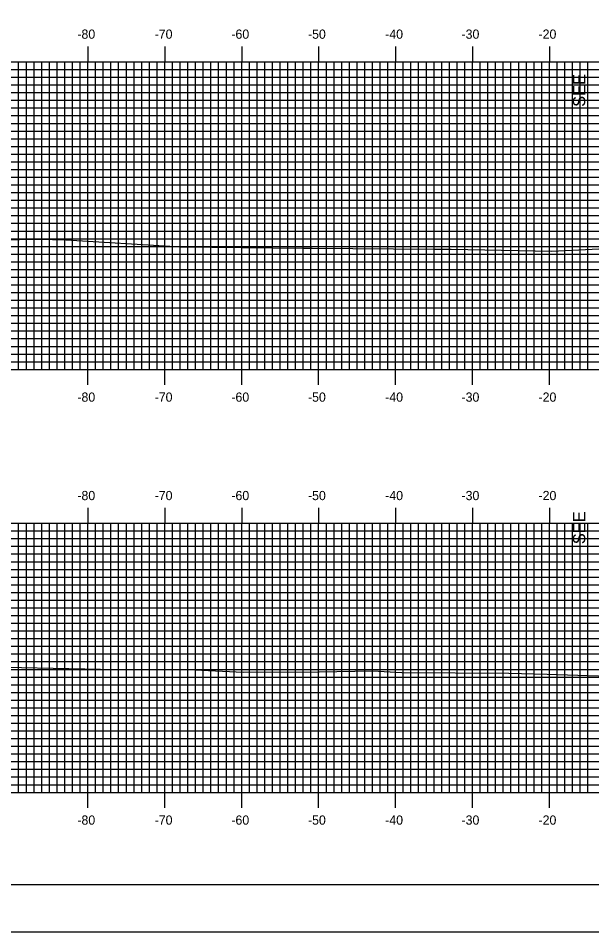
# Model space of a CAD drawing. Extents: x 854903 to 855247, y 364366 to 364586.
# Drawn here: x 854980.2 to 855054.8, y 364365.7 to 364484.5 of the extents above; entities that cross this region are included whole.
import ezdxf

# ---------------------------------------------------------------- set-up
doc = ezdxf.new("R2010")
doc.units = 0
for name, color, linetype in [('ANNOTATION', 7, 'Continuous'), ('BORDER', 7, 'Continuous'), ('H_V ANNOTATION', 7, 'Continuous'), ('MAJOR', 7, 'Continuous'), ('MINOR', 7, 'Continuous'), ('PLOT BOUNDARY', 7, 'Continuous'), ('S_Roadway_Centerline', 7, 'Continuous')]:
    doc.layers.add(name, color=color, linetype=linetype)

msp = doc.modelspace()

# ---------------------------------------------------------------- linework, layer by layer
at = {"layer": 'BORDER'}
msp.add_lwpolyline([(854919.66, 364371.79), (855239.66, 364371.79), (855239.66, 364581.79), (854919.66, 364581.79)], close=True, dxfattribs=at)
at = {"layer": 'MAJOR'}
for p, q in [((854989.26, 364480.79), (854989.26, 364478.79)), ((854999.26, 364480.79), (854999.26, 364478.79)), ((855009.26, 364480.79), (855009.26, 364478.79)), ((855019.26, 364480.79), (855019.26, 364478.79)), ((855029.26, 364480.79), (855029.26, 364478.79)), ((855039.26, 364480.79), (855039.26, 364478.79)), ((855049.26, 364480.79), (855049.26, 364478.79)), ((854929.26, 364478.79), (855209.26, 364478.79)), ((854929.26, 364478.79), (855209.26, 364478.79)), ((854989.26, 364438.79), (854989.26, 364478.79)), ((854999.26, 364438.79), (854999.26, 364478.79)), ((855009.26, 364438.79), (855009.26, 364478.79)), ((855019.26, 364438.79), (855019.26, 364478.79)), ((855029.26, 364438.79), (855029.26, 364478.79)), ((855039.26, 364438.79), (855039.26, 364478.79)), ((855049.26, 364438.79), (855049.26, 364478.79)), ((854929.26, 364473.79), (855209.26, 364473.79)), ((854929.26, 364468.79), (855209.26, 364468.79)), ((854929.26, 364463.79), (855209.26, 364463.79)), ((854929.26, 364458.79), (855209.26, 364458.79)), ((854929.26, 364453.79), (855209.26, 364453.79)), ((854929.26, 364448.79), (855209.26, 364448.79)), ((854929.26, 364443.79), (855209.26, 364443.79)), ((854929.26, 364438.79), (855209.26, 364438.79)), ((854929.26, 364438.79), (855209.26, 364438.79)), ((854989.26, 364436.78), (854989.26, 364438.79)), ((854999.26, 364436.78), (854999.26, 364438.79)), ((855009.26, 364436.78), (855009.26, 364438.79)), ((855019.26, 364436.78), (855019.26, 364438.79)), ((855029.26, 364436.78), (855029.26, 364438.79)), ((855039.26, 364436.78), (855039.26, 364438.79)), ((855049.26, 364436.78), (855049.26, 364438.79)), ((854989.26, 364420.79), (854989.26, 364418.79)), ((854999.26, 364420.79), (854999.26, 364418.79)), ((855009.26, 364420.79), (855009.26, 364418.79)), ((855019.26, 364420.79), (855019.26, 364418.79)), ((855029.26, 364420.79), (855029.26, 364418.79)), ((855039.26, 364420.79), (855039.26, 364418.79)), ((855049.26, 364420.79), (855049.26, 364418.79)), ((854929.26, 364418.79), (855209.26, 364418.79)), ((854929.26, 364418.79), (855209.26, 364418.79)), ((854989.26, 364383.79), (854989.26, 364418.79)), ((854999.26, 364383.79), (854999.26, 364418.79)), ((855009.26, 364383.79), (855009.26, 364418.79)), ((855019.26, 364383.79), (855019.26, 364418.79)), ((855029.26, 364383.79), (855029.26, 364418.79)), ((855039.26, 364383.79), (855039.26, 364418.79)), ((855049.26, 364383.79), (855049.26, 364418.79)), ((854929.26, 364413.79), (855209.26, 364413.79)), ((854929.26, 364408.79), (855209.26, 364408.79)), ((854929.26, 364403.79), (855209.26, 364403.79)), ((854929.26, 364398.79), (855209.26, 364398.79)), ((854929.26, 364393.79), (855209.26, 364393.79)), ((854929.26, 364388.79), (855209.26, 364388.79)), ((854929.26, 364383.79), (855209.26, 364383.79)), ((854929.26, 364383.79), (855209.26, 364383.79)), ((854989.26, 364381.78), (854989.26, 364383.79)), ((854999.26, 364381.78), (854999.26, 364383.79)), ((855009.26, 364381.78), (855009.26, 364383.79)), ((855019.26, 364381.78), (855019.26, 364383.79)), ((855029.26, 364381.78), (855029.26, 364383.79)), ((855039.26, 364381.78), (855039.26, 364383.79)), ((855049.26, 364381.78), (855049.26, 364383.79))]:
    msp.add_line(p, q, dxfattribs=at)
at = {"layer": 'MINOR'}
for p, q in [((854980.26, 364438.79), (854980.26, 364478.79)), ((854981.26, 364438.79), (854981.26, 364478.79)), ((854982.26, 364438.79), (854982.26, 364478.79)), ((854983.26, 364438.79), (854983.26, 364478.79)), ((854984.26, 364438.79), (854984.26, 364478.79)), ((854985.26, 364438.79), (854985.26, 364478.79)), ((854986.26, 364438.79), (854986.26, 364478.79)), ((854987.26, 364438.79), (854987.26, 364478.79)), ((854988.26, 364438.79), (854988.26, 364478.79)), ((854990.26, 364438.79), (854990.26, 364478.79)), ((854991.26, 364438.79), (854991.26, 364478.79)), ((854992.26, 364438.79), (854992.26, 364478.79)), ((854993.26, 364438.79), (854993.26, 364478.79)), ((854994.26, 364438.79), (854994.26, 364478.79)), ((854995.26, 364438.79), (854995.26, 364478.79)), ((854996.26, 364438.79), (854996.26, 364478.79)), ((854997.26, 364438.79), (854997.26, 364478.79)), ((854998.26, 364438.79), (854998.26, 364478.79)), ((855000.26, 364438.79), (855000.26, 364478.79)), ((855001.26, 364438.79), (855001.26, 364478.79)), ((855002.26, 364438.79), (855002.26, 364478.79)), ((855003.26, 364438.79), (855003.26, 364478.79)), ((855004.26, 364438.79), (855004.26, 364478.79)), ((855005.26, 364438.79), (855005.26, 364478.79)), ((855006.26, 364438.79), (855006.26, 364478.79)), ((855007.26, 364438.79), (855007.26, 364478.79)), ((855008.26, 364438.79), (855008.26, 364478.79)), ((855010.26, 364438.79), (855010.26, 364478.79)), ((855011.26, 364438.79), (855011.26, 364478.79)), ((855012.26, 364438.79), (855012.26, 364478.79)), ((855013.26, 364438.79), (855013.26, 364478.79)), ((855014.26, 364438.79), (855014.26, 364478.79)), ((855015.26, 364438.79), (855015.26, 364478.79)), ((855016.26, 364438.79), (855016.26, 364478.79)), ((855017.26, 364438.79), (855017.26, 364478.79)), ((855018.26, 364438.79), (855018.26, 364478.79)), ((855020.26, 364438.79), (855020.26, 364478.79)), ((855021.26, 364438.79), (855021.26, 364478.79)), ((855022.26, 364438.79), (855022.26, 364478.79)), ((855023.26, 364438.79), (855023.26, 364478.79)), ((855024.26, 364438.79), (855024.26, 364478.79)), ((855025.26, 364438.79), (855025.26, 364478.79)), ((855026.26, 364438.79), (855026.26, 364478.79)), ((855027.26, 364438.79), (855027.26, 364478.79)), ((855028.26, 364438.79), (855028.26, 364478.79)), ((855030.26, 364438.79), (855030.26, 364478.79)), ((855031.26, 364438.79), (855031.26, 364478.79)), ((855032.26, 364438.79), (855032.26, 364478.79)), ((855033.26, 364438.79), (855033.26, 364478.79)), ((855034.26, 364438.79), (855034.26, 364478.79)), ((855035.26, 364438.79), (855035.26, 364478.79)), ((855036.26, 364438.79), (855036.26, 364478.79)), ((855037.26, 364438.79), (855037.26, 364478.79)), ((855038.26, 364438.79), (855038.26, 364478.79)), ((855040.26, 364438.79), (855040.26, 364478.79)), ((855041.26, 364438.79), (855041.26, 364478.79)), ((855042.26, 364438.79), (855042.26, 364478.79)), ((855043.26, 364438.79), (855043.26, 364478.79)), ((855044.26, 364438.79), (855044.26, 364478.79)), ((855045.26, 364438.79), (855045.26, 364478.79)), ((855046.26, 364438.79), (855046.26, 364478.79)), ((855047.26, 364438.79), (855047.26, 364478.79)), ((855048.26, 364438.79), (855048.26, 364478.79)), ((855050.26, 364438.79), (855050.26, 364478.79)), ((855051.26, 364438.79), (855051.26, 364478.79)), ((855052.26, 364438.79), (855052.26, 364478.79)), ((855053.26, 364438.79), (855053.26, 364478.79)), ((855054.26, 364438.79), (855054.26, 364478.79)), ((854929.26, 364477.79), (855209.26, 364477.79)), ((854929.26, 364476.79), (855209.26, 364476.79)), ((854929.26, 364475.79), (855209.26, 364475.79)), ((854929.26, 364474.79), (855209.26, 364474.79)), ((854929.26, 364472.79), (855209.26, 364472.79)), ((854929.26, 364471.79), (855209.26, 364471.79)), ((854929.26, 364470.79), (855209.26, 364470.79)), ((854929.26, 364469.79), (855209.26, 364469.79)), ((854929.26, 364467.79), (855209.26, 364467.79)), ((854929.26, 364466.79), (855209.26, 364466.79)), ((854929.26, 364465.79), (855209.26, 364465.79)), ((854929.26, 364464.79), (855209.26, 364464.79)), ((854929.26, 364462.79), (855209.26, 364462.79)), ((854929.26, 364461.79), (855209.26, 364461.79)), ((854929.26, 364460.79), (855209.26, 364460.79)), ((854929.26, 364459.79), (855209.26, 364459.79)), ((854929.26, 364457.79), (855209.26, 364457.79)), ((854929.26, 364456.79), (855209.26, 364456.79)), ((854929.26, 364455.79), (855209.26, 364455.79)), ((854929.26, 364454.79), (855209.26, 364454.79)), ((854929.26, 364452.79), (855209.26, 364452.79)), ((854929.26, 364451.79), (855209.26, 364451.79)), ((854929.26, 364450.79), (855209.26, 364450.79)), ((854929.26, 364449.79), (855209.26, 364449.79)), ((854929.26, 364447.79), (855209.26, 364447.79)), ((854929.26, 364446.79), (855209.26, 364446.79)), ((854929.26, 364445.79), (855209.26, 364445.79)), ((854929.26, 364444.79), (855209.26, 364444.79)), ((854929.26, 364442.79), (855209.26, 364442.79)), ((854929.26, 364441.79), (855209.26, 364441.79)), ((854929.26, 364440.79), (855209.26, 364440.79)), ((854929.26, 364439.79), (855209.26, 364439.79)), ((854929.26, 364417.79), (855209.26, 364417.79)), ((854980.26, 364383.79), (854980.26, 364418.79)), ((854981.26, 364383.79), (854981.26, 364418.79)), ((854982.26, 364383.79), (854982.26, 364418.79)), ((854983.26, 364383.79), (854983.26, 364418.79)), ((854984.26, 364383.79), (854984.26, 364418.79)), ((854985.26, 364383.79), (854985.26, 364418.79)), ((854986.26, 364383.79), (854986.26, 364418.79)), ((854987.26, 364383.79), (854987.26, 364418.79)), ((854988.26, 364383.79), (854988.26, 364418.79)), ((854990.26, 364383.79), (854990.26, 364418.79)), ((854991.26, 364383.79), (854991.26, 364418.79)), ((854992.26, 364383.79), (854992.26, 364418.79)), ((854993.26, 364383.79), (854993.26, 364418.79)), ((854994.26, 364383.79), (854994.26, 364418.79)), ((854995.26, 364383.79), (854995.26, 364418.79)), ((854996.26, 364383.79), (854996.26, 364418.79)), ((854997.26, 364383.79), (854997.26, 364418.79)), ((854998.26, 364383.79), (854998.26, 364418.79)), ((855000.26, 364383.79), (855000.26, 364418.79)), ((855001.26, 364383.79), (855001.26, 364418.79)), ((855002.26, 364383.79), (855002.26, 364418.79)), ((855003.26, 364383.79), (855003.26, 364418.79)), ((855004.26, 364383.79), (855004.26, 364418.79)), ((855005.26, 364383.79), (855005.26, 364418.79)), ((855006.26, 364383.79), (855006.26, 364418.79)), ((855007.26, 364383.79), (855007.26, 364418.79)), ((855008.26, 364383.79), (855008.26, 364418.79)), ((855010.26, 364383.79), (855010.26, 364418.79)), ((855011.26, 364383.79), (855011.26, 364418.79)), ((855012.26, 364383.79), (855012.26, 364418.79)), ((855013.26, 364383.79), (855013.26, 364418.79)), ((855014.26, 364383.79), (855014.26, 364418.79)), ((855015.26, 364383.79), (855015.26, 364418.79)), ((855016.26, 364383.79), (855016.26, 364418.79)), ((855017.26, 364383.79), (855017.26, 364418.79)), ((855018.26, 364383.79), (855018.26, 364418.79)), ((855020.26, 364383.79), (855020.26, 364418.79)), ((855021.26, 364383.79), (855021.26, 364418.79)), ((855022.26, 364383.79), (855022.26, 364418.79)), ((855023.26, 364383.79), (855023.26, 364418.79)), ((855024.26, 364383.79), (855024.26, 364418.79)), ((855025.26, 364383.79), (855025.26, 364418.79)), ((855026.26, 364383.79), (855026.26, 364418.79)), ((855027.26, 364383.79), (855027.26, 364418.79)), ((855028.26, 364383.79), (855028.26, 364418.79)), ((855030.26, 364383.79), (855030.26, 364418.79)), ((855031.26, 364383.79), (855031.26, 364418.79)), ((855032.26, 364383.79), (855032.26, 364418.79)), ((855033.26, 364383.79), (855033.26, 364418.79)), ((855034.26, 364383.79), (855034.26, 364418.79)), ((855035.26, 364383.79), (855035.26, 364418.79)), ((855036.26, 364383.79), (855036.26, 364418.79)), ((855037.26, 364383.79), (855037.26, 364418.79)), ((855038.26, 364383.79), (855038.26, 364418.79)), ((855040.26, 364383.79), (855040.26, 364418.79)), ((855041.26, 364383.79), (855041.26, 364418.79)), ((855042.26, 364383.79), (855042.26, 364418.79)), ((855043.26, 364383.79), (855043.26, 364418.79)), ((855044.26, 364383.79), (855044.26, 364418.79)), ((855045.26, 364383.79), (855045.26, 364418.79)), ((855046.26, 364383.79), (855046.26, 364418.79)), ((855047.26, 364383.79), (855047.26, 364418.79)), ((855048.26, 364383.79), (855048.26, 364418.79)), ((855050.26, 364383.79), (855050.26, 364418.79)), ((855051.26, 364383.79), (855051.26, 364418.79)), ((855052.26, 364383.79), (855052.26, 364418.79)), ((855053.26, 364383.79), (855053.26, 364418.79)), ((855054.26, 364383.79), (855054.26, 364418.79)), ((854929.26, 364416.79), (855209.26, 364416.79)), ((854929.26, 364415.79), (855209.26, 364415.79)), ((854929.26, 364414.79), (855209.26, 364414.79)), ((854929.26, 364412.79), (855209.26, 364412.79)), ((854929.26, 364411.79), (855209.26, 364411.79)), ((854929.26, 364410.79), (855209.26, 364410.79)), ((854929.26, 364409.79), (855209.26, 364409.79)), ((854929.26, 364407.79), (855209.26, 364407.79)), ((854929.26, 364406.79), (855209.26, 364406.79)), ((854929.26, 364405.79), (855209.26, 364405.79)), ((854929.26, 364404.79), (855209.26, 364404.79)), ((854929.26, 364402.79), (855209.26, 364402.79)), ((854929.26, 364401.79), (855209.26, 364401.79)), ((854929.26, 364400.79), (855209.26, 364400.79)), ((854929.26, 364399.79), (855209.26, 364399.79)), ((854929.26, 364397.79), (855209.26, 364397.79)), ((854929.26, 364396.79), (855209.26, 364396.79)), ((854929.26, 364395.79), (855209.26, 364395.79)), ((854929.26, 364394.79), (855209.26, 364394.79)), ((854929.26, 364392.79), (855209.26, 364392.79)), ((854929.26, 364391.79), (855209.26, 364391.79)), ((854929.26, 364390.79), (855209.26, 364390.79)), ((854929.26, 364389.79), (855209.26, 364389.79)), ((854929.26, 364387.79), (855209.26, 364387.79)), ((854929.26, 364386.79), (855209.26, 364386.79)), ((854929.26, 364385.79), (855209.26, 364385.79)), ((854929.26, 364384.79), (855209.26, 364384.79))]:
    msp.add_line(p, q, dxfattribs=at)
at = {"layer": 'PLOT BOUNDARY'}
msp.add_lwpolyline([(854903.47, 364365.67), (855243.47, 364365.67), (855243.47, 364585.67), (854903.47, 364585.67)], close=True, dxfattribs=at)
at = {"layer": 'S_Roadway_Centerline'}
for points in [[(854929.26, 364455.65), (854930.12, 364455.64), (854935.39, 364455.7), (854940.01, 364455.61), (854952.05, 364455.61), (854966.09, 364455.5), (854968.49, 364455.49), (854970.28, 364455.56), (854983.7, 364455.72), (854984.67, 364455.69), (854985.69, 364455.67), (855001.36, 364454.71), (855001.44, 364454.71), (855017.22, 364454.55), (855017.35, 364454.55), (855018.41, 364454.54), (855034.27, 364454.44), (855036.5, 364454.42), (855049.55, 364454.18), (855062.67, 364454.82)], [(854929.26, 364400.09), (854934.94, 364400.14), (854942.39, 364400.15), (854956.95, 364400.54), (854959.01, 364400.56), (854960.38, 364400.58), (854968.31, 364400.32), (854974.18, 364400.14), (854975.07, 364400.15), (854976.45, 364400.12), (854992.99, 364399.77), (855003.15, 364399.71), (855009.46, 364399.41), (855019.32, 364399.48), (855026.25, 364399.61), (855030.09, 364399.38), (855043.99, 364399.28), (855048.97, 364399.15), (855058.3, 364398.86)]]:
    msp.add_lwpolyline(points, dxfattribs=at)

# ---------------------------------------------------------------- texts
at = {"layer": 'ANNOTATION'}
for p in [(855053.92, 364472.93), (855053.92, 364416.06)]:
    msp.add_text('SEE', height=1.6, rotation=90, dxfattribs=at).set_placement(p)
at = {"layer": 'H_V ANNOTATION'}
for s, p in [('-80', (854987.89, 364481.79)), ('-70', (854997.94, 364481.79)), ('-60', (855007.91, 364481.79)), ('-50', (855017.87, 364481.79)), ('-40', (855027.91, 364481.79)), ('-30', (855037.83, 364481.79)), ('-20', (855047.84, 364481.79)), ('-80', (854987.89, 364434.59)), ('-70', (854997.94, 364434.59)), ('-60', (855007.91, 364434.59)), ('-50', (855017.87, 364434.59)), ('-40', (855027.91, 364434.59)), ('-30', (855037.83, 364434.59)), ('-20', (855047.84, 364434.59)), ('-80', (854987.89, 364421.79)), ('-70', (854997.94, 364421.79)), ('-60', (855007.91, 364421.79)), ('-50', (855017.87, 364421.79)), ('-40', (855027.91, 364421.79)), ('-30', (855037.83, 364421.79)), ('-20', (855047.84, 364421.79)), ('-80', (854987.89, 364379.59)), ('-70', (854997.94, 364379.59)), ('-60', (855007.91, 364379.59)), ('-50', (855017.87, 364379.59)), ('-40', (855027.91, 364379.59)), ('-30', (855037.83, 364379.59)), ('-20', (855047.84, 364379.59))]:
    msp.add_text(s, height=1.2, dxfattribs=at).set_placement(p)

doc.saveas('drawing.dxf')
